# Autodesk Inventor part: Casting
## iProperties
Shininess: 77.0
Length Units: 11269
Angle Units: 11279
Time Units: 11290
Mass Units: 11283
Length Display Precision: 3
Angle Display Precision: 2
Created: 2002-02
Part Number: Casting
Document SubType Name: Modeling
Designer: ***
Stock Number: 01
Density: 0.0
Volumn: 0.0
Area: 0.0
PropertySet Name: Model Information
Control State: 0
Master: False
Checked Out: False
Author: ***
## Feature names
1. Extrusion1
2. Extrusion2
3. Extrusion3
4. Extrusion4
5. Extrusion5
6. Mirror1
7. Extrusion6
